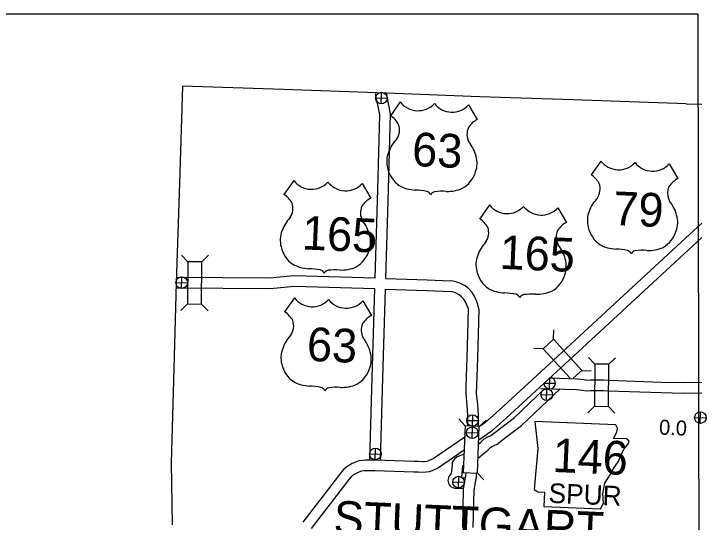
# Model space of a CAD drawing. Extents: x 1196286 to 1268366, y 2040822 to 2082115.
# Drawn here: x 1203681 to 1207588, y 2079249 to 2082115 of the extents above; entities that cross this region are included whole.
import ezdxf

# ---------------------------------------------------------------- set-up
doc = ezdxf.new("R2010")
doc.units = 0
for name, color, linetype in [('55', 7, 'Continuous'), ('Level 100', 7, 'Continuous'), ('Level 70', 7, 'Continuous'), ('Level 78', 7, 'Continuous'), ('Level 8', 7, 'Continuous'), ('Level 80', 7, 'Continuous'), ('Level 82', 7, 'Continuous'), ('Level 84', 7, 'Continuous'), ('Level 87', 7, 'Continuous'), ('Level 98', 7, 'Continuous')]:
    doc.layers.add(name, color=color, linetype=linetype)

msp = doc.modelspace()

# ---------------------------------------------------------------- linework, layer by layer
at = {"layer": '55'}
for points in [[(1207474.9, 2081607.9), (1206837.9, 2081629.8), (1206310.3, 2081646.8), (1205782.4, 2081667.1), (1205202.6, 2081688.7), (1204632, 2081707.9), (1204616.8, 2081158.3), (1204597.1, 2080598.6), (1204583.7, 2080115.1), (1204568.5, 2079583.1), (1204573.6, 2079234.1)], [(1207474.9, 2081607.9), (1207563, 2081605)]]:
    msp.add_lwpolyline(points, dxfattribs=at)
at = {"layer": 'Level 100'}
for p, q in [((1205754.7, 2081607.3), (1205756, 2081672.4)), ((1205722.8, 2081640.5), (1205787.9, 2081639.2)), ((1204627.6, 2080566.9), (1204628.9, 2080632)), ((1204595.7, 2080600), (1204660.8, 2080598.8)), ((1206704.6, 2080000.1), (1206705.8, 2080059.9)), ((1206672.7, 2080033.3), (1206737.8, 2080032)), ((1206687.4, 2079934.7), (1206688.7, 2079999.8)), ((1206655.5, 2079967.9), (1206720.6, 2079966.6)), ((1206269, 2079789.5), (1206270.3, 2079854.6)), ((1206237.1, 2079822.7), (1206302.2, 2079821.4)), ((1206267.4, 2079720.4), (1206268.7, 2079785.5)), ((1206235.5, 2079753.6), (1206300.6, 2079752.3)), ((1205688.5, 2079634.1), (1205753.6, 2079632.8)), ((1205720.5, 2079600.9), (1205721.7, 2079666)), ((1206158.2, 2079475.3), (1206223.3, 2079474)), ((1206190.1, 2079442.1), (1206191.4, 2079507.2))]:
    msp.add_line(p, q, dxfattribs=at)
for centre in [(1205755.3, 2081639.9), (1204628.2, 2080599.4), (1206688.1, 2079967.3), (1206269.7, 2079822.1), (1206268, 2079752.9), (1205721.1, 2079633.4), (1206190.8, 2079474.7)]:
    msp.add_circle(centre, 32.6, dxfattribs=at)
msp.add_arc((1206705.2, 2080032.7), 32.6, 185.4018, 81.7873, dxfattribs=at)
at = {"layer": 'Level 78'}
msp.add_lwpolyline([(1206621.4, 2079816.5), (1206637.7, 2079663.4), (1206617.7, 2079433.1), (1206637.4, 2079419.6), (1206675.5, 2079417.9), (1206672, 2079336.8), (1206991.5, 2079323.1), (1207008.1, 2079355.4), (1207005.3, 2079408.9), (1207015.5, 2079469.4), (1207045.5, 2079516.4), (1207064.7, 2079551.1), (1207091.7, 2079588.1), (1207108.7, 2079628), (1207122.7, 2079660.4), (1207146.8, 2079687.3), (1207152.6, 2079704.9), (1207143, 2079718), (1207064.4, 2079721.3), (1207083.7, 2079756.1), (1207087.2, 2079778.8), (1207077.4, 2079796.8)], close=True, dxfattribs=at)
at = {"layer": 'Level 8'}
msp.add_lwpolyline([(1196285.8, 2082114.9), (1207540.7, 2082114.9), (1207563, 2069523.3), (1196285.8, 2069523.3)], close=True, dxfattribs=at)
at = {"layer": 'Level 80'}
for p, q in [((1205861.8, 2081618), (1205806.5, 2081540)), ((1206247.6, 2081601.5), (1206296, 2081519.1)), ((1206993.8, 2081285.2), (1206938.5, 2081207.2)), ((1207379.5, 2081268.7), (1207428, 2081186.2)), ((1205260.7, 2081174.8), (1205205.4, 2081096.8)), ((1205646.4, 2081158.3), (1205694.9, 2081075.8)), ((1206365.2, 2081037.9), (1206309.9, 2080959.8)), ((1206750.9, 2081021.3), (1206799.3, 2080938.9)), ((1205264.6, 2080512.8), (1205209.3, 2080434.8)), ((1205650.3, 2080496.3), (1205698.8, 2080413.9))]:
    msp.add_line(p, q, dxfattribs=at)
for centre, radius, start, end in [((1205961.9, 2081695.2), 126.4, 217.623, 317.2181), ((1206154.4, 2081686.9), 126.4, 217.8778, 317.4729), ((1205733.7, 2081426.5), 134.9, 28.3289, 57.5362), ((1206358.8, 2081399.7), 134.9, 117.5597, 146.767), ((1205764.9, 2081460.7), 92.5, 326.3584, 18.7587), ((1206330.7, 2081436.5), 92.5, 156.3372, 208.7375), ((1205998.4, 2081261), 215.7, 136.5044, 160.2393), ((1206080.9, 2081257.5), 215.7, 14.8566, 38.5915), ((1205928, 2081281.7), 142.6, 158.5056, 194.9298), ((1206152.8, 2081272.1), 142.6, 340.1661, 16.5903), ((1207093.9, 2081362.3), 126.4, 217.623, 317.2181), ((1207286.4, 2081354.1), 126.4, 217.8778, 317.4729), ((1205951.2, 2081281.1), 165, 192.6554, 234.6791), ((1206129.7, 2081273.5), 165, 300.4168, 342.4405), ((1206865.7, 2081093.6), 134.9, 28.3289, 57.5362), ((1205360.8, 2081251.9), 126.4, 217.623, 317.2181), ((1205553.3, 2081243.7), 126.4, 217.8778, 317.4729), ((1206896.9, 2081127.9), 92.5, 326.3584, 18.7587), ((1207490.8, 2081066.8), 134.9, 117.5597, 146.767), ((1205956.5, 2081332.9), 211.8, 241.625, 267.1258), ((1205935.8, 2080733.5), 388, 78.7421, 88.5018), ((1205999.1, 2081079), 37.2, 25.5822, 70.5343), ((1206098.3, 2080726.5), 388, 86.5941, 96.3538), ((1206128.8, 2081325.5), 211.8, 267.9701, 293.4709), ((1207462.6, 2081103.7), 92.5, 156.3372, 208.7375), ((1205132.6, 2080983.2), 134.9, 28.3289, 57.5362), ((1205757.7, 2080956.4), 134.9, 117.5597, 146.767), ((1206064.7, 2081076.2), 37.2, 104.5616, 149.5137), ((1207130.4, 2080928.1), 215.7, 136.5044, 160.2393), ((1205163.8, 2081017.5), 92.5, 326.3584, 18.7587), ((1206465.3, 2081115), 126.4, 217.623, 317.2181), ((1207212.9, 2080924.6), 215.7, 14.8566, 38.5915), ((1205729.5, 2080993.3), 92.5, 156.3372, 208.7375), ((1206657.8, 2081106.8), 126.4, 217.8778, 317.4729), ((1207060, 2080948.9), 142.6, 158.5056, 194.9298), ((1205397.3, 2080817.8), 215.7, 136.5044, 160.2393), ((1206237.1, 2080846.3), 134.9, 28.3289, 57.5362), ((1207284.8, 2080939.2), 142.6, 340.1661, 16.5903), ((1205479.8, 2080814.2), 215.7, 14.8566, 38.5915), ((1206862.1, 2080819.5), 134.9, 117.5597, 146.767), ((1205326.9, 2080838.5), 142.6, 158.5056, 194.9298), ((1206268.3, 2080880.6), 92.5, 326.3584, 18.7587), ((1206834, 2080856.3), 92.5, 156.3372, 208.7375), ((1207083.2, 2080948.3), 165, 192.6554, 234.6791), ((1207261.6, 2080940.6), 165, 300.4168, 342.4405), ((1205551.7, 2080828.8), 142.6, 340.1661, 16.5903), ((1205350.1, 2080837.9), 165, 192.6554, 234.6791), ((1206501.8, 2080680.8), 215.7, 136.5044, 160.2393), ((1206584.3, 2080677.3), 215.7, 14.8566, 38.5915), ((1207088.5, 2081000), 211.8, 241.625, 267.1258), ((1205528.6, 2080830.2), 165, 300.4168, 342.4405), ((1207067.7, 2080400.6), 388, 78.7421, 88.5018), ((1207131.1, 2080746.1), 37.2, 25.5822, 70.5343), ((1207196.7, 2080743.3), 37.2, 104.5616, 149.5137), ((1207230.2, 2080393.7), 388, 86.5941, 96.3538), ((1207260.8, 2080992.7), 211.8, 267.9701, 293.4709), ((1206431.4, 2080701.5), 142.6, 158.5056, 194.9298), ((1206656.2, 2080691.9), 142.6, 340.1661, 16.5903), ((1205355.4, 2080889.6), 211.8, 241.625, 267.1258), ((1205527.7, 2080882.3), 211.8, 267.9701, 293.4709), ((1205334.6, 2080290.2), 388, 78.7421, 88.5018), ((1205398, 2080635.7), 37.2, 25.5822, 70.5343), ((1205463.6, 2080632.9), 37.2, 104.5616, 149.5137), ((1205497.2, 2080283.3), 388, 86.5941, 96.3538), ((1206454.6, 2080700.9), 165, 192.6554, 234.6791), ((1206633, 2080693.3), 165, 300.4168, 342.4405), ((1206459.9, 2080752.7), 211.8, 241.625, 267.1258), ((1206439.1, 2080153.3), 388, 78.7421, 88.5018), ((1206502.5, 2080498.8), 37.2, 25.5822, 70.5343), ((1206568, 2080496), 37.2, 104.5616, 149.5137), ((1206601.6, 2080146.3), 388, 86.5941, 96.3538), ((1206632.2, 2080745.3), 211.8, 267.9701, 293.4709), ((1205364.7, 2080590), 126.4, 217.623, 317.2181), ((1205557.2, 2080581.7), 126.4, 217.8778, 317.4729), ((1205136.5, 2080321.2), 134.9, 28.3289, 57.5362), ((1205761.6, 2080294.5), 134.9, 117.5597, 146.767), ((1205167.7, 2080355.5), 92.5, 326.3584, 18.7587), ((1205733.5, 2080331.3), 92.5, 156.3372, 208.7375), ((1205401.2, 2080155.8), 215.8, 136.5044, 160.2393), ((1205483.7, 2080152.2), 215.8, 14.8566, 38.5915), ((1205330.8, 2080176.5), 142.6, 158.5056, 194.9298), ((1205555.6, 2080166.9), 142.6, 340.1661, 16.5903), ((1205354, 2080175.9), 165, 192.6554, 234.6791), ((1205532.5, 2080168.3), 165, 300.4168, 342.4405), ((1205359.3, 2080227.7), 211.8, 241.625, 267.1258), ((1205531.6, 2080220.3), 211.8, 267.9701, 293.4709), ((1205338.5, 2079628.2), 388, 78.7421, 88.5018), ((1205401.9, 2079973.7), 37.2, 25.5822, 70.5343), ((1205467.5, 2079970.9), 37.2, 104.5616, 149.5137), ((1205501.1, 2079621.3), 388, 86.5941, 96.3538)]:
    msp.add_arc(centre, radius, start, end, dxfattribs=at)
at = {"layer": 'Level 82'}
for p, q in [((1207554.7, 2079805.8), (1207556, 2079870.9)), ((1207522.8, 2079839), (1207587.9, 2079837.8))]:
    msp.add_line(p, q, dxfattribs=at)
msp.add_circle((1207555.3, 2079838.4), 32.6, dxfattribs=at)
at = {"layer": 'Level 84'}
for points in [[(1205720.8, 2080624.9), (1205735.5, 2081125.4), (1205747.1, 2081545.8), (1205722.8, 2081665.5)], [(1205780.8, 2080622.1), (1205795.5, 2081123.7), (1205807.3, 2081551.1), (1205783.6, 2081667.3)], [(1207447.5, 2080828.2), (1207563, 2080934.8)], [(1207488.2, 2080784.1), (1207563, 2080853.2)], [(1207447.5, 2080828.2), (1206773.5, 2080205.6), (1206419.1, 2079880.2), (1206337.6, 2079807.8), (1206307.8, 2079786.5)], [(1207488.2, 2080784.1), (1206814.2, 2080161.4), (1206459.3, 2079835.7), (1206375.1, 2079760.8), (1206304.5, 2079710.5)], [(1205720.8, 2080624.7), (1205262.1, 2080638), (1205124.1, 2080623.8), (1204596.7, 2080629.1)], [(1205780.8, 2080622.1), (1206013.8, 2080614.6), (1206148.1, 2080610.3)], [(1206305.6, 2080451), (1206299, 2080476.9), (1206292.8, 2080497.4), (1206282.8, 2080519.4), (1206267.1, 2080544.2), (1206248.4, 2080564), (1206227.5, 2080580.7), (1206198.4, 2080597.1), (1206169.6, 2080606.6), (1206148.1, 2080610.3)], [(1205690, 2079600.7), (1205703, 2080064.4), (1205719, 2080564.7), (1205264.3, 2080578), (1205126.9, 2080563.8), (1204596.1, 2080569.1)], [(1205749.9, 2079596.9), (1205763, 2080062.6), (1205778.9, 2080562.1)], [(1205778.9, 2080562.1), (1206011.9, 2080554.7), (1206148.8, 2080550.3)], [(1206245.7, 2080455.9), (1206229.9, 2080490.8), (1206219.5, 2080507.2), (1206207.7, 2080519.8), (1206193.8, 2080530.8), (1206174, 2080542), (1206148.8, 2080550.3)], [(1206245.7, 2080455.9), (1206241, 2080307.9), (1206236.9, 2080178), (1206233.5, 2080072), (1206231.6, 2080003.9), (1206230.8, 2079972.2)], [(1206305.6, 2080451), (1206301, 2080306), (1206296.8, 2080176.1), (1206293.5, 2080070.2), (1206290.8, 2079974.8)], [(1206230.8, 2079972.2), (1206237, 2079907.9), (1206240.8, 2079849.6), (1206240.5, 2079791.7)], [(1206290.8, 2079974.8), (1206296.8, 2079912.7), (1206300.8, 2079851.4), (1206300.5, 2079789.2)], [(1206226, 2079728.5), (1206046.8, 2079606.7), (1206021.2, 2079594.3), (1206011.2, 2079591.7), (1206001.1, 2079589.8), (1205989.8, 2079589.5), (1205963.3, 2079590.1), (1205939.3, 2079590.6), (1205719.8, 2079597.7), (1205665.5, 2079598.7), (1205650.2, 2079596.9), (1205628.2, 2079594.3), (1205605.6, 2079585.6), (1205590.2, 2079579.2), (1205574.8, 2079570.6), (1205559.9, 2079561.6), (1205542.7, 2079547.3), (1205524.7, 2079525.5), (1205513.1, 2079509.6), (1205311.3, 2079249)], [(1206222.9, 2079653.8), (1206076.9, 2079554.7), (1206042, 2079537.7), (1206024.4, 2079533.2), (1206007.5, 2079529.9), (1205989.9, 2079529.5), (1205962, 2079530.1), (1205937.7, 2079530.6), (1205718.3, 2079537.8), (1205668.6, 2079538.7), (1205657.3, 2079537.3), (1205642.7, 2079535.6), (1205627.8, 2079529.9), (1205616.3, 2079525.1), (1205605, 2079518.8), (1205594.8, 2079512.6), (1205585.3, 2079504.7), (1205572.1, 2079488.7), (1205561, 2079473.6), (1205358.7, 2079212.3)], [(1206230.9, 2079528.7), (1206230.4, 2079510.1), (1206217.3, 2079437.4)], [(1206290.9, 2079526.2), (1206290.2, 2079503.8), (1206277.2, 2079431.3)], [(1206217.3, 2079437.4), (1206212.1, 2079219.2)], [(1206277.2, 2079431.3), (1206272.1, 2079217.8)]]:
    msp.add_lwpolyline(points, dxfattribs=at)
at = {"layer": 'Level 87'}
for points in [[(1206708.5, 2080061.7), (1206860.9, 2080057.3), (1206881.6, 2080055.3), (1206899.2, 2080052.4), (1206914.4, 2080050.2), (1206934.4, 2080050.5), (1206966.9, 2080051.1), (1207009.5, 2080050.6), (1207038.5, 2080049.9), (1207333.7, 2080038.9), (1207461.5, 2080036.9)], [(1207461, 2080037), (1207563, 2080037.3)], [(1206507.1, 2079839.3), (1206678.3, 2080001.9)], [(1206545.9, 2079793.4), (1206763.4, 2079999.9)], [(1206652.5, 2080003.3), (1206857.1, 2079997.4), (1206873.8, 2079995.8), (1206890, 2079993.1), (1206910.6, 2079990.1), (1206935.4, 2079990.5), (1206967.1, 2079991.1), (1207008.4, 2079990.6), (1207036.6, 2079989.9), (1207332.1, 2079979), (1207460.6, 2079977)], [(1207461.2, 2079977), (1207563, 2079977.3)], [(1206303.7, 2079690.1), (1206315.9, 2079700.5), (1206326.7, 2079709.9), (1206336.1, 2079717.9), (1206339.9, 2079720.7), (1206342.4, 2079722.4), (1206344.9, 2079724.1), (1206347.7, 2079725.7), (1206350.6, 2079727.3), (1206352.5, 2079728.1), (1206354.1, 2079729), (1206368.5, 2079735.8), (1206378.1, 2079740.7), (1206378.4, 2079741), (1206380.4, 2079742.6), (1206390.3, 2079750), (1206400.4, 2079758.9), (1206419.5, 2079773.4), (1206507.1, 2079839.3)], [(1206300.1, 2079606.8), (1206339.3, 2079641.6), (1206346.6, 2079647.8), (1206355.1, 2079655), (1206366, 2079664.6), (1206373.3, 2079670.8), (1206374.4, 2079671.6), (1206376.1, 2079672.7), (1206377, 2079673.4), (1206378.6, 2079674.1), (1206380.9, 2079675.3), (1206395.1, 2079682), (1206409.2, 2079689.3), (1206413.5, 2079692.3), (1206415.8, 2079694), (1206417.2, 2079695.2), (1206428.1, 2079703.4), (1206438.5, 2079712.5), (1206455.7, 2079725.6), (1206545.9, 2079793.4)], [(1206221.9, 2079632.3), (1206182.2, 2079616.2), (1206167.8, 2079604.4), (1206160.4, 2079594.3), (1206155.3, 2079584.4), (1206153.9, 2079573.1), (1206152.1, 2079553.1), (1206148.8, 2079523.1)], [(1206219.2, 2079567.7), (1206213.5, 2079565.7), (1206211.8, 2079547.1), (1206206.5, 2079499.8)], [(1206148.8, 2079523.1), (1206142.3, 2079514.4), (1206136.4, 2079506.7), (1206133.4, 2079499.6), (1206131.3, 2079492.1), (1206130.7, 2079483.7), (1206131.5, 2079475.9), (1206133.7, 2079468), (1206137.4, 2079461.5), (1206142, 2079454.8), (1206149, 2079448.2), (1206157.6, 2079443.5), (1206168.2, 2079440.8), (1206174.7, 2079440.4), (1206217.7, 2079439.6)], [(1206206.5, 2079499.8), (1206228.4, 2079499.4)]]:
    msp.add_lwpolyline(points, dxfattribs=at)
at = {"layer": 'Level 98'}
for p, q in [((1204663.4, 2080717.2), (1204626.4, 2080754.9)), ((1204742.6, 2080716.4), (1204780.3, 2080753.4)), ((1204661, 2080479.6), (1204623.3, 2080442.7)), ((1204740.2, 2080478.8), (1204777.1, 2080441.1)), ((1206725.9, 2080279.9), (1206728.1, 2080332.6)), ((1206725.9, 2080279.9), (1206667.5, 2080226.3)), ((1206886.5, 2080104.8), (1206725.9, 2080279.9)), ((1206667.5, 2080226.3), (1206614.8, 2080228.6)), ((1206667.5, 2080226.3), (1206819.7, 2080060.6)), ((1206960.1, 2080140), (1206923.2, 2080177.8)), ((1207039.3, 2080139), (1207077, 2080175.9)), ((1206837.5, 2080059.8), (1206886.5, 2080104.8)), ((1206886.5, 2080104.8), (1206939.3, 2080102.6)), ((1206957.3, 2079902.4), (1206919.5, 2079865.5)), ((1207036.5, 2079901.5), (1207073.3, 2079863.7)), ((1206228.7, 2079792.2), (1206193, 2079831.1)), ((1206307.9, 2079788.8), (1206346.8, 2079824.6)), ((1206296.7, 2079525.9), (1206307.9, 2079788.8)), ((1206217.6, 2079529.3), (1206296.7, 2079525.9)), ((1206296.7, 2079525.9), (1206332.4, 2079487.1))]:
    msp.add_line(p, q, dxfattribs=at)
for points in [[(1204740.2, 2080478.8), (1204742.6, 2080716.4), (1204663.4, 2080717.2), (1204661, 2080479.6)], [(1206960.1, 2080140), (1206957.3, 2079902.4), (1207036.5, 2079901.5), (1207039.3, 2080139)]]:
    msp.add_lwpolyline(points, close=True, dxfattribs=at)
msp.add_lwpolyline([(1206307.9, 2079788.8), (1206228.7, 2079792.2), (1206217.6, 2079529.3)], dxfattribs=at)

# ---------------------------------------------------------------- texts
at = {"layer": 'Level 70'}
msp.add_text('STUTTGART', height=190.08, rotation=357.548, dxfattribs=at).set_placement((1205483, 2079180.2))
at = {"layer": 'Level 78'}
for s, height, p in [('146', 190.08, (1206718.3, 2079532.2)), ('SPUR', 110.88, (1206696.9, 2079358.3))]:
    msp.add_text(s, height=height, rotation=357.548, dxfattribs=at).set_placement(p)
at = {"layer": 'Level 80'}
for s, height, p in [('63', 190.08, (1205925.8, 2081257.3)), ('79', 190.08, (1207060.7, 2080924.3)), ('165', 190.08, (1205304.2, 2080787)), ('165', 190.08, (1206419.4, 2080677.7)), ('63', 190.09, (1205332.1, 2080158.7))]:
    msp.add_text(s, height=height, rotation=357.548, dxfattribs=at).set_placement(p)
at = {"layer": 'Level 82'}
msp.add_text('0.0', height=84.48, rotation=357.548, dxfattribs=at).set_placement((1207320.9, 2079742.8))

doc.saveas('drawing.dxf')
